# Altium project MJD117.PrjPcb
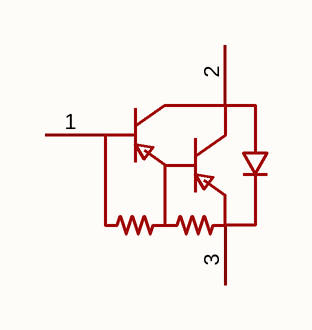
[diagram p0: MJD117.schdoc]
1 sheet, 1 parts. Net scope: global (net labels, ports and power ports of the same name join across sheets).

## Sheet MJD117.schdoc
size 127 x 101 mm

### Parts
Q?  mjd117  [TO-252-2_L6.6-W6.1-P4.60-LS10.0-BR-CW]  (value not drawn)

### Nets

Not connected (* = marked no-connect by the designer): Q? 1(B) 2(C) 3(E)

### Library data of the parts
Q? = mjd117: 晶体管类型:PNP;集电极电流(Ic):2A;集射极击穿电压(Vceo):100V;耗散功率(Pd):1.75W;直流电流增益(hFE):500;; Manufacturer: CJ(江苏长电/长晶); AddInBom: yes; ModelId: 2bfbfbb77002446c96d8a76a432e0188; ModelTransform: 246.80147,383.8575,0,90,0,0,-31.302,0.003,0; type: PNP; Current - Collector(Ic): 2A; Collector - Emitter Voltage VCEO: 100V; Pd - Power Dissipation: 1.75W; DC Current Gain: 500; Transition frequency(fT): 25MHz; Current - Collector Cutoff: 10uA; Vce Saturation(VCE(sat)): 3V; Emitter-Base Voltage(Vebo): 5V; Number: 1个PNP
